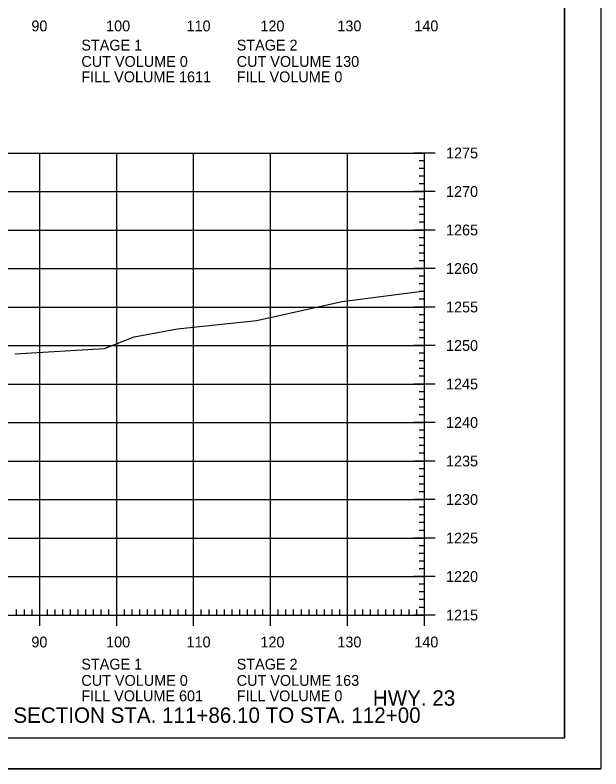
# Model space of a CAD drawing. Extents: x 1406028 to 1412453, y 321733 to 325986.
# Drawn here: x 1406676.7 to 1406752.8, y 323212.7 to 323310.6 of the extents above; entities that cross this region are included whole.
import ezdxf

# ---------------------------------------------------------------- set-up
doc = ezdxf.new("R2010")
doc.units = 0
for name, color, linetype in [('R_Axis', 7, 'Continuous'), ('R_Axis Annot', 7, 'Continuous'), ('R_Border', 7, 'Continuous'), ('R_Draft', 7, 'Continuous'), ('R_Exist Surface', 7, 'Continuous'), ('R_Grid', 7, 'Continuous'), ('R_No Plot', 7, 'Continuous')]:
    doc.layers.add(name, color=color, linetype=linetype)

msp = doc.modelspace()

# ---------------------------------------------------------------- linework, layer by layer
at = {"layer": 'R_Axis'}
for p, q in [((1406731.29, 323292.679), (1406728.49, 323292.679)), ((1406729.89, 323232.679), (1406729.89, 323292.679)), ((1406729.89, 323291.679), (1406729.19, 323291.679)), ((1406729.89, 323290.679), (1406729.19, 323290.679)), ((1406729.89, 323289.679), (1406729.19, 323289.679)), ((1406729.89, 323288.679), (1406729.19, 323288.679)), ((1406731.29, 323287.679), (1406728.49, 323287.679)), ((1406729.89, 323286.679), (1406729.19, 323286.679)), ((1406729.89, 323285.679), (1406729.19, 323285.679)), ((1406729.89, 323284.679), (1406729.19, 323284.679)), ((1406729.89, 323283.679), (1406729.19, 323283.679)), ((1406731.29, 323282.679), (1406728.49, 323282.679)), ((1406729.89, 323281.679), (1406729.19, 323281.679)), ((1406729.89, 323280.679), (1406729.19, 323280.679)), ((1406729.89, 323279.679), (1406729.19, 323279.679)), ((1406729.89, 323278.679), (1406729.19, 323278.679)), ((1406731.29, 323277.679), (1406728.49, 323277.679)), ((1406729.89, 323276.679), (1406729.19, 323276.679)), ((1406729.89, 323275.679), (1406729.19, 323275.679)), ((1406729.89, 323274.679), (1406729.19, 323274.679)), ((1406729.89, 323273.679), (1406729.19, 323273.679)), ((1406731.29, 323272.679), (1406728.49, 323272.679)), ((1406729.89, 323271.679), (1406729.19, 323271.679)), ((1406729.89, 323270.679), (1406729.19, 323270.679)), ((1406729.89, 323269.679), (1406729.19, 323269.679)), ((1406729.89, 323268.679), (1406729.19, 323268.679)), ((1406731.29, 323267.679), (1406728.49, 323267.679)), ((1406729.89, 323266.679), (1406729.19, 323266.679)), ((1406729.89, 323265.679), (1406729.19, 323265.679)), ((1406729.89, 323264.679), (1406729.19, 323264.679)), ((1406729.89, 323263.679), (1406729.19, 323263.679)), ((1406731.29, 323262.679), (1406728.49, 323262.679)), ((1406729.89, 323261.679), (1406729.19, 323261.679)), ((1406729.89, 323260.679), (1406729.19, 323260.679)), ((1406729.89, 323259.679), (1406729.19, 323259.679)), ((1406729.89, 323258.679), (1406729.19, 323258.679)), ((1406731.29, 323257.679), (1406728.49, 323257.679)), ((1406729.89, 323256.679), (1406729.19, 323256.679)), ((1406729.89, 323255.679), (1406729.19, 323255.679)), ((1406729.89, 323254.679), (1406729.19, 323254.679)), ((1406729.89, 323253.679), (1406729.19, 323253.679)), ((1406731.29, 323252.679), (1406728.49, 323252.679)), ((1406729.89, 323251.679), (1406729.19, 323251.679)), ((1406729.89, 323250.679), (1406729.19, 323250.679)), ((1406729.89, 323249.679), (1406729.19, 323249.679)), ((1406729.89, 323248.679), (1406729.19, 323248.679)), ((1406731.29, 323247.679), (1406728.49, 323247.679)), ((1406729.89, 323246.679), (1406729.19, 323246.679)), ((1406729.89, 323245.679), (1406729.19, 323245.679)), ((1406729.89, 323244.679), (1406729.19, 323244.679)), ((1406729.89, 323243.679), (1406729.19, 323243.679)), ((1406731.29, 323242.679), (1406728.49, 323242.679)), ((1406729.89, 323241.679), (1406729.19, 323241.679)), ((1406729.89, 323240.679), (1406729.19, 323240.679)), ((1406729.89, 323239.679), (1406729.19, 323239.679)), ((1406729.89, 323238.679), (1406729.19, 323238.679)), ((1406731.29, 323237.679), (1406728.49, 323237.679)), ((1406729.89, 323236.679), (1406729.19, 323236.679)), ((1406729.89, 323235.679), (1406729.19, 323235.679)), ((1406729.89, 323234.679), (1406729.19, 323234.679)), ((1406676.89, 323232.679), (1406676.89, 323233.379)), ((1406677.89, 323232.679), (1406677.89, 323233.379)), ((1406678.89, 323232.679), (1406678.89, 323233.379)), ((1406679.89, 323231.279), (1406679.89, 323234.079)), ((1406680.89, 323232.679), (1406680.89, 323233.379)), ((1406681.89, 323232.679), (1406681.89, 323233.379)), ((1406682.89, 323232.679), (1406682.89, 323233.379)), ((1406683.89, 323232.679), (1406683.89, 323233.379)), ((1406684.89, 323232.679), (1406684.89, 323233.379)), ((1406685.89, 323232.679), (1406685.89, 323233.379)), ((1406686.89, 323232.679), (1406686.89, 323233.379)), ((1406687.89, 323232.679), (1406687.89, 323233.379)), ((1406688.89, 323232.679), (1406688.89, 323233.379)), ((1406689.89, 323231.279), (1406689.89, 323234.079)), ((1406690.89, 323232.679), (1406690.89, 323233.379)), ((1406691.89, 323232.679), (1406691.89, 323233.379)), ((1406692.89, 323232.679), (1406692.89, 323233.379)), ((1406693.89, 323232.679), (1406693.89, 323233.379)), ((1406694.89, 323232.679), (1406694.89, 323233.379)), ((1406695.89, 323232.679), (1406695.89, 323233.379)), ((1406696.89, 323232.679), (1406696.89, 323233.379)), ((1406697.89, 323232.679), (1406697.89, 323233.379)), ((1406698.89, 323232.679), (1406698.89, 323233.379)), ((1406699.89, 323231.279), (1406699.89, 323234.079)), ((1406700.89, 323232.679), (1406700.89, 323233.379)), ((1406701.89, 323232.679), (1406701.89, 323233.379)), ((1406702.89, 323232.679), (1406702.89, 323233.379)), ((1406703.89, 323232.679), (1406703.89, 323233.379)), ((1406704.89, 323232.679), (1406704.89, 323233.379)), ((1406705.89, 323232.679), (1406705.89, 323233.379)), ((1406706.89, 323232.679), (1406706.89, 323233.379)), ((1406707.89, 323232.679), (1406707.89, 323233.379)), ((1406708.89, 323232.679), (1406708.89, 323233.379)), ((1406709.89, 323231.279), (1406709.89, 323234.079)), ((1406710.89, 323232.679), (1406710.89, 323233.379)), ((1406711.89, 323232.679), (1406711.89, 323233.379)), ((1406712.89, 323232.679), (1406712.89, 323233.379)), ((1406713.89, 323232.679), (1406713.89, 323233.379)), ((1406714.89, 323232.679), (1406714.89, 323233.379)), ((1406715.89, 323232.679), (1406715.89, 323233.379)), ((1406716.89, 323232.679), (1406716.89, 323233.379)), ((1406717.89, 323232.679), (1406717.89, 323233.379)), ((1406718.89, 323232.679), (1406718.89, 323233.379)), ((1406719.89, 323231.279), (1406719.89, 323234.079)), ((1406720.89, 323232.679), (1406720.89, 323233.379)), ((1406721.89, 323232.679), (1406721.89, 323233.379)), ((1406722.89, 323232.679), (1406722.89, 323233.379)), ((1406723.89, 323232.679), (1406723.89, 323233.379)), ((1406724.89, 323232.679), (1406724.89, 323233.379)), ((1406725.89, 323232.679), (1406725.89, 323233.379)), ((1406726.89, 323232.679), (1406726.89, 323233.379)), ((1406727.89, 323232.679), (1406727.89, 323233.379)), ((1406728.89, 323232.679), (1406728.89, 323233.379)), ((1406729.89, 323233.679), (1406729.19, 323233.679)), ((1406729.89, 323231.279), (1406729.89, 323234.079)), ((1406449.89, 323232.679), (1406729.89, 323232.679)), ((1406731.29, 323232.679), (1406728.49, 323232.679))]:
    msp.add_line(p, q, dxfattribs=at)
at = {"layer": 'R_Border'}
for q in [(1406748.07, 323422.139), (1406431.89, 323216.679)]:
    msp.add_line((1406748.07, 323216.679), q, dxfattribs=at)
at = {"layer": 'R_Exist Surface'}
msp.add_lwpolyline([(1406676.662, 323266.584), (1406688.31, 323267.302), (1406692.163, 323268.817), (1406697.795, 323269.828), (1406708.057, 323270.924), (1406719.207, 323273.383), (1406729.89, 323274.783)], dxfattribs=at)
at = {"layer": 'R_Grid'}
for p, q in [((1406449.89, 323292.679), (1406729.89, 323292.679)), ((1406679.89, 323232.679), (1406679.89, 323292.679)), ((1406689.89, 323232.679), (1406689.89, 323292.679)), ((1406699.89, 323232.679), (1406699.89, 323292.679)), ((1406709.89, 323232.679), (1406709.89, 323292.679)), ((1406719.89, 323232.679), (1406719.89, 323292.679)), ((1406729.89, 323232.679), (1406729.89, 323292.679)), ((1406449.89, 323287.679), (1406729.89, 323287.679)), ((1406449.89, 323282.679), (1406729.89, 323282.679)), ((1406449.89, 323277.679), (1406729.89, 323277.679)), ((1406449.89, 323272.679), (1406729.89, 323272.679)), ((1406449.89, 323267.679), (1406729.89, 323267.679)), ((1406449.89, 323262.679), (1406729.89, 323262.679)), ((1406449.89, 323257.679), (1406729.89, 323257.679)), ((1406449.89, 323252.679), (1406729.89, 323252.679)), ((1406449.89, 323247.679), (1406729.89, 323247.679)), ((1406449.89, 323242.679), (1406729.89, 323242.679)), ((1406449.89, 323237.679), (1406729.89, 323237.679)), ((1406449.89, 323232.679), (1406729.89, 323232.679))]:
    msp.add_line(p, q, dxfattribs=at)
at = {"layer": 'R_No Plot'}
msp.add_line((1406419.489, 323212.701), (1406752.822, 323212.701), dxfattribs=at)
for points in [[(1406419.482, 323426.034), (1406752.822, 323426.034), (1406752.822, 323212.696), (1406419.482, 323212.696)], [(1406665.81, 323422.139), (1406685.43, 323422.139), (1406685.43, 323412.259), (1406701.542, 323412.259), (1406724.741, 323412.259), (1406724.741, 323387.927), (1406748.07, 323387.927), (1406748.07, 323216.679), (1406431.89, 323216.679), (1406431.89, 323422.139)]]:
    msp.add_lwpolyline(points, close=True, dxfattribs=at)

# ---------------------------------------------------------------- texts
at = {"layer": 'R_Axis Annot'}
for s, p in [('90', (1406678.804, 323308.479)), ('100', (1406688.517, 323308.479)), ('110', (1406698.969, 323308.479)), ('120', (1406708.572, 323308.479)), ('130', (1406718.572, 323308.479)), ('140', (1406728.572, 323308.479)), ('STAGE 1', (1406685.298, 323305.987)), ('STAGE 2', (1406705.489, 323305.987)), ('CUT VOLUME 0', (1406685.298, 323303.868)), ('CUT VOLUME 130', (1406705.489, 323303.868)), ('FILL VOLUME 1611', (1406685.298, 323301.868)), ('FILL VOLUME 0', (1406705.489, 323301.868)), ('1275', (1406732.69, 323291.979)), ('1270', (1406732.69, 323286.979)), ('1265', (1406732.69, 323281.979)), ('1260', (1406732.69, 323276.979)), ('1255', (1406732.69, 323271.979)), ('1250', (1406732.69, 323266.979)), ('1245', (1406732.69, 323261.979)), ('1240', (1406732.69, 323256.979)), ('1235', (1406732.69, 323251.979)), ('1230', (1406732.69, 323246.979)), ('1225', (1406732.69, 323241.979)), ('1220', (1406732.69, 323236.979)), ('1215', (1406732.69, 323231.979)), ('90', (1406678.804, 323228.479)), ('100', (1406688.517, 323228.479)), ('110', (1406698.969, 323228.479)), ('120', (1406708.572, 323228.479)), ('130', (1406718.572, 323228.479)), ('140', (1406728.572, 323228.479)), ('STAGE 1', (1406685.298, 323225.605)), ('STAGE 2', (1406705.489, 323225.605)), ('CUT VOLUME 0', (1406685.298, 323223.487)), ('CUT VOLUME 163', (1406705.489, 323223.487)), ('FILL VOLUME 601', (1406685.298, 323221.487)), ('FILL VOLUME 0', (1406705.489, 323221.487))]:
    msp.add_text(s, height=1.4, dxfattribs=at).set_placement(p)
at = {"layer": 'R_Draft'}
for s, p in [('HWY. 23', (1406723.186, 323220.911)), ('CROSS SECTION STA. 111+86.10 TO STA. 112+00', (1406666.216, 323218.679))]:
    msp.add_text(s, height=2, dxfattribs=at).set_placement(p)
at = {"layer": 'R_No Plot'}
for p in [(1406708.014, 323270.874), (1406688.267, 323267.252)]:
    msp.add_text('+', height=0.1, dxfattribs=at).set_placement(p)

doc.saveas('drawing.dxf')
